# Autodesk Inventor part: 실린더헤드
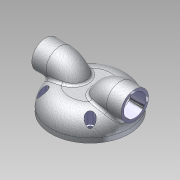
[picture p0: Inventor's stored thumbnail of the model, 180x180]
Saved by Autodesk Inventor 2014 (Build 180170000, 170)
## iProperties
Manager: KYOUNG IL JANG
Company: 한국ATC센터
Created: 2012-10
Part Number: 실린더헤드
Document SubType Name: Modeling
Density: 1 g/cm^3
Checked By: KYOUNG IL JANG
Vendor: CBT Solutions
Designer: KYOUNG IL JANG
Material: 일반
Appearance: _시험_알루미늄 표면거칠기
Author: KYOUNG IL JANG
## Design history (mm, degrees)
sketch "스케치1"
  geometry: C1 r 42.5 at (0, 0); 1 further point
  constraints: 1 centre point, 1 coincident
  dimensions: "d0" = 85 diameter of C1
extrude "돌출1" new body sketch "스케치1" distance "d1" = 25; taper "d2" = 0 deg
fillet "모깎기1" dims "d3" = 20
sketch "스케치2"
  geometry: C1 r 30 at (0, 0); 1 further point
  constraints: 1 centre point, 1 coincident
  dimensions: "d4" = 60 diameter of C1
extrude "돌출2" join sketch "스케치2" distance "d5" = 5; taper "d6" = 0 deg
sketch "스케치3"
  geometry: L1 (-42.5, 0)-(42.5, 0) reference; L2 (-48.5, 30)-(-33, 30); L3 (-17.545, 18.141)-(-12.684, 0); A1 r 16 centre (-33, 14) between (-17.545, 18.141) and (-33, 30); 1 further point
  constraints: 4 end point, 2 point on circle, 2 tangent, 1 centre point, 1 parallel, 1 point on line
  dimensions: "d7" = 16 radius of A1; "d8" = 6 horizontal distance of L2.start L1.start; "d9" = 30 distance between parallel lines of L2 L1; "d11" = 105 deg angle of L3 L1; "d36" = 15.5 distance of L2.start L2.end
node "작업 평면1"
sketch "스케치4"
  geometry: C1 r 15 at (0, 0); C2 r 12 at (0, 0); 2 further points
  constraints: 2 centre point, 2 coincident
  dimensions: "d12" = 30 diameter of C1; "d13" = 3 radial gap between concentric circles of C2 C1
feature "스윕1" dims "d14" = 0
feature "스윕2" dims "d15" = 0
sketch "스케치5"
  geometry: L1 (30, -5)-(-30, -5) reference; L2 (0, -5)-(0, 10); L3 (0, 10)-(-10, 10); A1 r 15 centre (-10, -5) between (-10, 10) and (-25, -5); 1 further point
  constraints: 4 end point, 2 perpendicular, 2 point on circle, 1 centre point, 1 midpoint, 1 point on line, 1 tangent
  dimensions: "d16" = 15 distance of L2.start L2.end; "d17" = 15 radius of A1; "d18" = 5 distance of L1.end A1.end
revolve "회전1" sketch "스케치5" stored, may be unused: angle "d19" = 90 deg
fillet "모깎기2" dims "d20" = 3
node "작업 평면2"
sketch "스케치6"
  geometry: L1 (0, 0)-(36.25, 0); C1 r 4.75 at (25.633, 25.633); C2 r 2.75 at (25.633, 25.633); A1 r 36.25 centre (0, 0) between (25.633, 25.633) and (36.25, 0); 1 further point
  constraints: 3 centre point, 2 coincident, 2 end point, 2 point on circle, 1 horizontal
  dimensions: "d22" = 72.5 diameter of A1; "d23" = 5.5 diameter of C2; "d24" = 9.5 diameter of C1; "d37" = 45 deg dimension on point (0, 0) C1.centre L1.end
extrude "돌출3" cut sketch "스케치6" stored distance "d25" = 5; taper "d26" = 0 deg
extrude "돌출4" cut sketch "스케치6" stored distance "d27" = 5; taper "d28" = 0 deg
chamfer "모따기1" distance "d33" = 1; stored, may be unused: second distance "d34" = 2, angle "d35" = 45 deg
node "솔리드1"
mirror "대칭1"
pattern_circular "원형 패턴1" dims angle "d30" = 360 deg
